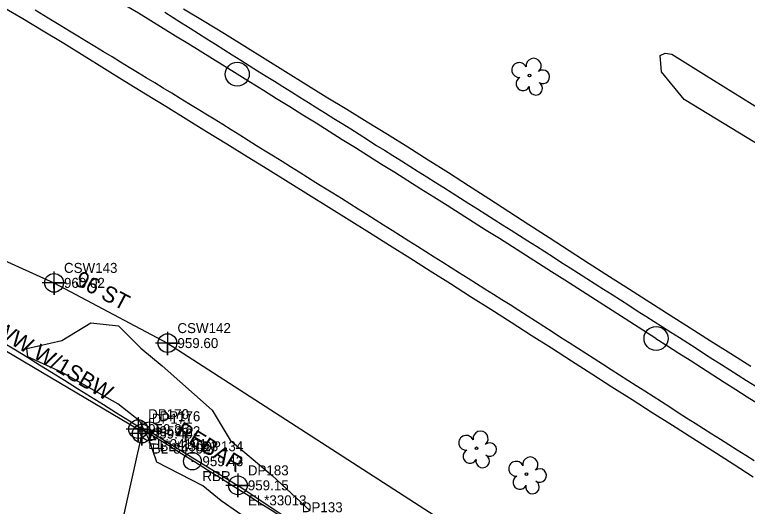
# Model space of a CAD drawing. Extents: x 1182322 to 1186765, y 572295 to 575411.
# Drawn here: x 1183900.4 to 1184083.8, y 573984.8 to 574107.9 of the extents above; entities that cross this region are included whole.
import ezdxf

# ---------------------------------------------------------------- set-up
doc = ezdxf.new("R2010")
doc.units = 0
for name, color, linetype in [('COGO Default Chain', 7, 'Continuous'), ('Exist Guardrail Cogo Comment', 7, 'Continuous'), ('Exist Guardrail Cogo Elevation', 7, 'Continuous'), ('Exist Guardrail Cogo Number', 7, 'Continuous'), ('Exist Guardrail Cogo Point CELL', 7, 'Continuous'), ('Exist Horizontal Alignment', 7, 'Continuous'), ('Exist Horizontal Alignment Point', 7, 'Continuous'), ('Exist Other Culture Fence Line', 7, 'Continuous'), ('Exist Other Culture Fence Line Cogo Comment', 7, 'Continuous'), ('Exist Other Culture Fence Line Cogo Elevation', 7, 'Continuous'), ('Exist Other Culture Fence Line Cogo Number', 7, 'Continuous'), ('Exist Other Culture Fence Line Cogo Point CELL', 7, 'Continuous'), ('Exist Other Culture Fence Line Text', 7, 'Continuous'), ('Exist Property Iron Pin CELL', 7, 'Continuous'), ('Exist Property Iron Pin Cogo Comment', 7, 'Continuous'), ('Exist Property Iron Pin Cogo Elevation', 7, 'Continuous'), ('Exist Property Iron Pin Cogo Number', 7, 'Continuous'), ('Exist Property Iron Pin Text', 7, 'Continuous'), ('Exist Right of Way Line', 7, 'Continuous'), ('Exist Right of Way Monument Cogo Number', 7, 'Continuous'), ('Exist Roads EOP', 7, 'Continuous'), ('Exist Roads EOT', 7, 'Continuous'), ('Exist Utilities Telephone UG Conduit SUE LOS B', 7, 'Continuous'), ('Exist Utilities Telephone UG Conduit SUE LOS B Cogo Elevation', 7, 'Continuous'), ('Exist Utilities Telephone UG Conduit SUE LOS B Cogo Number', 7, 'Continuous'), ('Exist Utilities Telephone UG Conduit SUE LOS B Cogo Point CELL', 7, 'Continuous'), ('Exist Utilities Telephone UG Conduit SUE LOS B Text', 7, 'Continuous'), ('Exist Vegetation Tree CELL', 7, 'Continuous'), ('Exist Vegetation Woods Line', 7, 'Continuous')]:
    doc.layers.add(name, color=color, linetype=linetype)

msp = doc.modelspace()

# ---------------------------------------------------------------- linework, layer by layer
at = {"layer": 'COGO Default Chain'}
for centre, radius, start, end in [((1182063.85, 571051.5), 3582.07, 58.1119, 59.97226), ((1179021.49, 566161.49), 9341.26, 57.351741, 58.1119), ((1195941.73, 592569.89), 22022.71, 237.351741, 237.915207)]:
    msp.add_arc(centre, radius, start, end, dxfattribs=at)
at = {"layer": 'Exist Guardrail Cogo Point CELL'}
for points in [[(1183934.15, 574006.57), (1183934.15, 574000.57), (1183934.15, 574003.57), (1183937.15, 574003.57), (1183931.15, 574003.57)], [(1183956.27, 573993.02), (1183956.27, 573987.02), (1183956.27, 573990.02), (1183959.27, 573990.02), (1183953.27, 573990.02)]]:
    msp.add_lwpolyline(points, dxfattribs=at)
for centre in [(1183934.15, 574003.57), (1183956.27, 573990.02)]:
    msp.add_circle(centre, 2.34, dxfattribs=at)
at = {"layer": 'Exist Horizontal Alignment'}
for centre, radius, start, end in [((1182063.85, 571051.5), 3582.07, 58.1119, 59.97226), ((1179021.49, 566161.49), 9341.26, 57.351741, 58.1119), ((1195941.73, 592569.89), 22022.71, 237.351741, 237.915207)]:
    msp.add_arc(centre, radius, start, end, dxfattribs=at)
at = {"layer": 'Exist Horizontal Alignment Point'}
for centre in [(1183956.13, 574092.97), (1184060.92, 574026.81)]:
    msp.add_circle(centre, 3, dxfattribs=at)
at = {"layer": 'Exist Other Culture Fence Line'}
msp.add_line((1183934.15, 574003.57), (1183956.27, 573990.02), dxfattribs=at)
for points in [[(1182431.26, 574477.6), (1182493.19, 574461.53), (1182576.37, 574440.23), (1182660.35, 574418.61), (1182745.71, 574396.94), (1182831.35, 574374.93), (1182917.06, 574353.23), (1182998.89, 574331.88), (1183080.06, 574310.08), (1183166.11, 574287.18), (1183252.15, 574263.83), (1183335.82, 574241.7), (1183417.69, 574219.73), (1183503.47, 574196.43), (1183592.65, 574167.54), (1183679.28, 574135.7), (1183764.86, 574099.44), (1183841.01, 574057.63), (1183931.32, 574004.09)], [(1183932.23, 574002.98), (1183926.85, 573978.68), (1183918.75, 573940.86), (1183914.77, 573921.3), (1183909.53, 573901.07)], [(1184129.53, 573878.39), (1184114.9, 573888.31), (1184094.64, 573900.8), (1184058.94, 573923.99), (1183975.11, 573977.38), (1183956.27, 573990.02)]]:
    msp.add_lwpolyline(points, dxfattribs=at)
at = {"layer": 'Exist Other Culture Fence Line Cogo Point CELL'}
for points in [[(1183931.32, 574007.09), (1183931.32, 574001.09), (1183931.32, 574004.09), (1183934.32, 574004.09), (1183928.32, 574004.09)], [(1183932.23, 574005.98), (1183932.23, 573999.98), (1183932.23, 574002.98), (1183935.23, 574002.98), (1183929.23, 574002.98)]]:
    msp.add_lwpolyline(points, dxfattribs=at)
for centre in [(1183931.32, 574004.09), (1183932.23, 574002.98)]:
    msp.add_circle(centre, 2.34, dxfattribs=at)
at = {"layer": 'Exist Property Iron Pin CELL'}
for radius in [2.2, 0.0707]:
    msp.add_circle((1183944.9, 573996.07), radius, dxfattribs=at)
at = {"layer": 'Exist Right of Way Line'}
for centre, radius, start, end in [((1183856.39, 574152.8), 88, 239.9723, 239.9723), ((1182063.85, 571051.5), 3494.07, 58.1119, 59.97226), ((1179021.49, 566161.49), 9253.26, 57.351741, 58.1119)]:
    msp.add_arc(centre, radius, start, end, dxfattribs=at)
at = {"layer": 'Exist Roads EOP'}
for points in [[(1184085.27, 573992.08), (1184080.22, 573995.32), (1184075.18, 573998.56), (1184070.12, 574001.78), (1184065.05, 574004.98), (1184059.99, 574008.19), (1184054.92, 574011.4), (1184049.86, 574014.61), (1184044.82, 574017.85), (1184039.77, 574021.09), (1184034.73, 574024.33), (1184029.69, 574027.57), (1184024.63, 574030.79), (1184019.57, 574034.01), (1184014.52, 574037.23), (1184009.46, 574040.45), (1184004.4, 574043.67), (1183999.32, 574046.87), (1183994.22, 574050.08), (1183989.18, 574053.25), (1183984.1, 574056.45), (1183979.02, 574059.63), (1183973.93, 574062.8), (1183968.84, 574065.96), (1183963.74, 574069.12), (1183958.64, 574072.27), (1183953.54, 574075.42), (1183948.43, 574078.57), (1183943.33, 574081.72), (1183938.23, 574084.86), (1183933.12, 574088.01), (1183928.02, 574091.16), (1183922.92, 574094.32), (1183917.82, 574097.47), (1183912.72, 574100.63), (1183907.59, 574103.72), (1183902.44, 574106.8), (1183897.29, 574109.87)], [(1183942.68, 574109.38), (1183947.82, 574106.29), (1183952.96, 574103.2), (1183958.05, 574100.03), (1183963.14, 574096.85), (1183968.22, 574093.67), (1183973.31, 574090.49), (1183978.41, 574087.34), (1183983.52, 574084.2), (1183988.63, 574081.06), (1183993.74, 574077.93), (1183998.83, 574074.75), (1184003.9, 574071.56), (1184008.98, 574068.37), (1184014.03, 574065.13), (1184019.05, 574061.85), (1184024.07, 574058.57), (1184029.1, 574055.32), (1184034.14, 574052.07), (1184039.18, 574048.82), (1184044.22, 574045.57), (1184049.27, 574042.34), (1184054.32, 574039.12), (1184059.38, 574035.89), (1184064.43, 574032.67), (1184069.49, 574029.45), (1184074.55, 574026.24), (1184079.62, 574023.03), (1184084.68, 574019.82)]]:
    msp.add_lwpolyline(points, dxfattribs=at)
at = {"layer": 'Exist Roads EOT'}
for points in [[(1184085.47, 573996.16), (1184083.36, 573997.5), (1184081.25, 573998.83), (1184079.13, 574000.16), (1184077.02, 574001.49), (1184074.91, 574002.82), (1184072.79, 574004.15), (1184070.69, 574005.5), (1184068.59, 574006.86), (1184066.49, 574008.21), (1184064.39, 574009.57), (1184062.3, 574010.92), (1184060.2, 574012.27), (1184058.09, 574013.62), (1184055.98, 574014.96), (1184053.88, 574016.3), (1184051.77, 574017.64), (1184049.66, 574018.98), (1184047.56, 574020.33), (1184045.45, 574021.67), (1184043.35, 574023.02), (1184041.25, 574024.37), (1184039.15, 574025.72), (1184037.05, 574027.08), (1184034.95, 574028.43), (1184032.85, 574029.79), (1184030.75, 574031.14), (1184028.65, 574032.49), (1184026.55, 574033.84), (1184024.44, 574035.18), (1184022.33, 574036.51), (1184020.21, 574037.84), (1184018.1, 574039.18), (1184015.99, 574040.51), (1184013.88, 574041.84), (1184011.76, 574043.17), (1184009.65, 574044.51), (1184007.54, 574045.84), (1184005.42, 574047.17), (1184003.31, 574048.5), (1184001.2, 574049.84), (1183999.08, 574051.17), (1183996.97, 574052.5), (1183994.85, 574053.83), (1183992.74, 574055.16), (1183990.63, 574056.49), (1183988.51, 574057.82), (1183986.4, 574059.16), (1183984.28, 574060.49), (1183982.17, 574061.82), (1183980.05, 574063.15), (1183977.94, 574064.47), (1183975.82, 574065.79), (1183973.7, 574067.12), (1183971.58, 574068.44), (1183969.46, 574069.76), (1183967.34, 574071.09), (1183965.22, 574072.41), (1183963.1, 574073.73), (1183960.98, 574075.06), (1183958.86, 574076.38), (1183956.74, 574077.7), (1183954.62, 574079.03), (1183952.5, 574080.35), (1183950.38, 574081.67), (1183948.26, 574082.99), (1183946.13, 574084.29), (1183944, 574085.59), (1183941.86, 574086.89), (1183939.73, 574088.19), (1183937.6, 574089.49), (1183935.46, 574090.79), (1183933.33, 574092.09), (1183931.19, 574093.39), (1183929.06, 574094.69), (1183926.93, 574095.99), (1183924.79, 574097.29), (1183922.66, 574098.59), (1183920.52, 574099.89), (1183918.39, 574101.19), (1183916.25, 574102.48), (1183914.12, 574103.78), (1183911.98, 574105.08), (1183909.85, 574106.37), (1183907.71, 574107.67), (1183905.57, 574108.97)], [(1183937.97, 574108.51), (1183940.08, 574107.18), (1183942.2, 574105.85), (1183944.31, 574104.52), (1183946.43, 574103.18), (1183948.54, 574101.85), (1183950.66, 574100.52), (1183952.77, 574099.19), (1183954.88, 574097.85), (1183957, 574096.52), (1183959.11, 574095.19), (1183961.22, 574093.85), (1183963.34, 574092.52), (1183965.45, 574091.19), (1183967.57, 574089.87), (1183969.69, 574088.54), (1183971.81, 574087.22), (1183973.93, 574085.89), (1183976.05, 574084.57), (1183978.17, 574083.24), (1183980.28, 574081.92), (1183982.4, 574080.59), (1183984.52, 574079.26), (1183986.62, 574077.92), (1183988.73, 574076.58), (1183990.84, 574075.24), (1183992.95, 574073.91), (1183995.07, 574072.58), (1183997.19, 574071.25), (1183999.31, 574069.93), (1184001.43, 574068.61), (1184003.55, 574067.28), (1184005.66, 574065.96), (1184007.78, 574064.63), (1184009.89, 574063.29), (1184012, 574061.95), (1184014.11, 574060.61), (1184016.21, 574059.27), (1184018.32, 574057.93), (1184020.43, 574056.59), (1184022.54, 574055.26), (1184024.65, 574053.92), (1184026.76, 574052.58), (1184028.87, 574051.24), (1184030.98, 574049.9), (1184033.08, 574048.55), (1184035.19, 574047.21), (1184037.29, 574045.86), (1184039.4, 574044.52), (1184041.5, 574043.17), (1184043.6, 574041.83), (1184045.71, 574040.48), (1184047.81, 574039.13), (1184049.92, 574037.79), (1184052.02, 574036.44), (1184054.13, 574035.1), (1184056.23, 574033.75), (1184058.34, 574032.41), (1184060.44, 574031.06), (1184062.55, 574029.72), (1184064.65, 574028.37), (1184066.76, 574027.03), (1184068.86, 574025.68), (1184070.97, 574024.34), (1184073.07, 574022.99), (1184075.18, 574021.65), (1184077.28, 574020.3), (1184079.39, 574018.96), (1184081.49, 574017.61), (1184083.6, 574016.27), (1184085.7, 574014.92)]]:
    msp.add_lwpolyline(points, dxfattribs=at)
at = {"layer": 'Exist Utilities Telephone UG Conduit SUE LOS B'}
msp.add_lwpolyline([(1183184.2, 574290.24), (1183230.46, 574277.8), (1183276.74, 574264.86), (1183322.88, 574252.13), (1183369.36, 574239.84), (1183416.41, 574227.82), (1183461.9, 574217.61), (1183507.97, 574205.1), (1183555.78, 574190.97), (1183600.29, 574174.7), (1183642.38, 574158.78), (1183685.83, 574141.54), (1183729.44, 574124.53), (1183772.61, 574105.48), (1183815.48, 574084.72), (1183856.9, 574064.89), (1183910.26, 574040.72), (1183938.65, 574025.64), (1184017.13, 573974.93), (1184056.25, 573949.51), (1184095.95, 573918.75), (1184120.25, 573896.12), (1184153.18, 573876.37), (1184177.6, 573863.32)], dxfattribs=at)
at = {"layer": 'Exist Utilities Telephone UG Conduit SUE LOS B Cogo Point CELL'}
for points in [[(1183910.25, 574043.54), (1183910.28, 574037.72), (1183910.26, 574040.72), (1183913.28, 574040.72), (1183907.28, 574040.72)], [(1183938.63, 574028.46), (1183938.66, 574022.64), (1183938.65, 574025.64), (1183941.66, 574025.64), (1183935.66, 574025.64)]]:
    msp.add_lwpolyline(points, dxfattribs=at)
for centre in [(1183910.28, 574040.72), (1183938.66, 574025.64)]:
    msp.add_circle(centre, 2.34, dxfattribs=at)
at = {"layer": 'Exist Vegetation Tree CELL'}
for p, q in [((1184029.26, 574092.65), (1184029.26, 574092.65)), ((1184015.99, 573999.3), (1184015.99, 573999.3)), ((1184028.48, 573992.81), (1184028.48, 573992.81))]:
    msp.add_line(p, q, dxfattribs=at)
for centre in [(1184029.26, 574092.65), (1184015.99, 573999.3), (1184028.48, 573992.81)]:
    msp.add_circle(centre, 0.326, dxfattribs=at)
for centre, radius, start, end in [((1184026.7, 574094.01), 1.86, 24.5374, 274.0857), ((1184030.27, 574095.06), 1.9, 311.4735, 188.5723), ((1184032.6, 574092.32), 1.7, 235.6545, 128.9324), ((1184027.62, 574090.62), 1.73, 117.036, 333.7181), ((1184030.81, 574089.45), 1.69, 165.9394, 60.6034), ((1184017, 574001.71), 1.9, 311.4735, 188.5723), ((1184013.43, 574000.66), 1.86, 24.5374, 274.0857), ((1184019.32, 573998.97), 1.7, 235.6545, 128.9324), ((1184014.35, 573997.27), 1.73, 117.036, 333.7181), ((1184017.53, 573996.09), 1.69, 165.9394, 60.6034), ((1184029.48, 573995.22), 1.9, 311.4735, 188.5723), ((1184025.92, 573994.17), 1.86, 24.5374, 274.0857), ((1184031.81, 573992.48), 1.7, 235.6545, 128.9324), ((1184026.84, 573990.78), 1.73, 117.036, 333.7181), ((1184030.02, 573989.61), 1.69, 165.9394, 60.6034)]:
    msp.add_arc(centre, radius, start, end, dxfattribs=at)
at = {"layer": 'Exist Vegetation Woods Line'}
msp.add_lwpolyline([(1184072.89, 574092.97), (1184106.72, 574071.95), (1184119.58, 574062.23), (1184117.44, 574058.22), (1184109.09, 574061.57), (1184067.99, 574086.6), (1184062.29, 574093.54), (1184061.92, 574097.63), (1184063.17, 574098.27), (1184064.87, 574097.95)], close=True, dxfattribs=at)
msp.add_lwpolyline([(1183964.35, 573977.64), (1183952.09, 573986.12), (1183947.49, 573989.88), (1183935.99, 573995.8), (1183934.06, 574001.41), (1183931.76, 574006.05), (1183926.26, 574010.45), (1183912.33, 574018.28), (1183903.74, 574022.17), (1183903.45, 574024.31), (1183912.24, 574026.27), (1183919.51, 574030.7), (1183926.41, 574029.98), (1183932, 574024.35), (1183937.36, 574019.94), (1183949.83, 574008.84), (1183954.37, 574001.29), (1183964.85, 573992.46), (1183974.34, 573983.65)], dxfattribs=at)

# ---------------------------------------------------------------- texts
at = {"layer": 'Exist Guardrail Cogo Comment'}
for s, p in [('BL*33013', (1183936.65, 573998.57)), ('EL*33013', (1183958.77, 573985.02))]:
    msp.add_text(s, height=2.5, dxfattribs=at).set_placement(p)
at = {"layer": 'Exist Guardrail Cogo Elevation'}
for s, p in [('959.22', (1183936.65, 574002.32)), ('959.15', (1183958.77, 573988.77))]:
    msp.add_text(s, height=2.5, dxfattribs=at).set_placement(p)
at = {"layer": 'Exist Guardrail Cogo Number'}
for s, p in [('DP176', (1183936.65, 574006.07)), ('DP183', (1183958.77, 573992.52))]:
    msp.add_text(s, height=2.5, dxfattribs=at).set_placement(p)
at = {"layer": 'Exist Other Culture Fence Line Cogo Comment'}
for s, p in [('EL*34101', (1183933.82, 573999.09)), ('BL*34102', (1183934.73, 573997.98))]:
    msp.add_text(s, height=2.5, dxfattribs=at).set_placement(p)
at = {"layer": 'Exist Other Culture Fence Line Cogo Elevation'}
for s, p in [('959.35', (1183933.82, 574002.84)), ('959.40', (1183934.73, 574001.73))]:
    msp.add_text(s, height=2.5, dxfattribs=at).set_placement(p)
at = {"layer": 'Exist Other Culture Fence Line Cogo Number'}
for s, p in [('DP170', (1183933.82, 574006.59)), ('DP171', (1183934.73, 574005.48))]:
    msp.add_text(s, height=2.5, dxfattribs=at).set_placement(p)
at = {"layer": 'Exist Other Culture Fence Line Text'}
msp.add_text('48" WW W/1SBW', height=4, rotation=329.3421, dxfattribs=at).set_placement((1183886.79, 574032.81))
at = {"layer": 'Exist Property Iron Pin Cogo Comment'}
msp.add_text('RBR', height=2.5, dxfattribs=at).set_placement((1183947.4, 573991.07))
at = {"layer": 'Exist Property Iron Pin Cogo Elevation'}
msp.add_text('959.43', height=2.5, dxfattribs=at).set_placement((1183947.4, 573994.82))
at = {"layer": 'Exist Property Iron Pin Cogo Number'}
msp.add_text('DP134', height=2.5, dxfattribs=at).set_placement((1183947.4, 573998.57))
at = {"layer": 'Exist Property Iron Pin Text'}
msp.add_text('REBAR', height=4, rotation=328.4416, dxfattribs=at).set_placement((1183940.36, 574002.76))
at = {"layer": 'Exist Right of Way Monument Cogo Number'}
msp.add_text('DP133', height=2.5, dxfattribs=at).set_placement((1183972.28, 573983.28))
at = {"layer": 'Exist Utilities Telephone UG Conduit SUE LOS B Cogo Elevation'}
for s, p in [('960.02', (1183912.76, 574039.47)), ('959.60', (1183941.15, 574024.39))]:
    msp.add_text(s, height=2.5, dxfattribs=at).set_placement(p)
at = {"layer": 'Exist Utilities Telephone UG Conduit SUE LOS B Cogo Number'}
for s, p in [('CSW143', (1183912.76, 574043.22)), ('CSW142', (1183941.15, 574028.14))]:
    msp.add_text(s, height=2.5, dxfattribs=at).set_placement(p)
at = {"layer": 'Exist Utilities Telephone UG Conduit SUE LOS B Text'}
msp.add_text('96 ST', height=4, rotation=332.0156, dxfattribs=at).set_placement((1183915.17, 574040.38))

doc.saveas('drawing.dxf')
